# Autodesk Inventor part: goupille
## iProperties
Shininess: 20.0
Length Units: 11269
Angle Units: 11279
Time Units: 11290
Mass Units: 11283
Length Display Precision: 3
Angle Display Precision: 2
Compacted: True
Created: 2003-02
Part Number: goupille
Material: Acier inoxydable - 440C
Document SubType Name: Modélisation
Designer: robert
Density: 7.75 g/cm^3
Density: 0.0
Volumn: 0.0
Area: 0.0
PropertySet Name: Model Information
Control State: 0
Master: False
Checked Out: False
Author: robert
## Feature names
1. Extrusion1
2. Chanfrein1 [Chamfer]
